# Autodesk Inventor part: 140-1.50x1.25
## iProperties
Created: 2007-06
Part Number: 140-1.50x1.25
Document SubType Name: Modeling
Designer: btaylor
Density: 1 g/cm^3
Author: btaylor
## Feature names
1. Extrusion1
2. Extrusion2
3. Chamfer1
4. Extrusion3
5. Fillet1
6. Chamfer2
